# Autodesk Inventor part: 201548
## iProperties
Created: 2007-10
Part Number: 201548
Document SubType Name: Modeling
Designer: TH
Density: 1.06 g/cm^3
Mass: 17.0659 g
Surface Area: 97.1751 cm^2
Volume: 16.0999 cm^3
Material: ABS Plastic
Description: WORM GEAR HOUSING
Component Category: Lower Component
Author: TH
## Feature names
1. Extrusion1
2. Extrusion2
3. Extrusion3
4. Extrusion4
5. Fillet1
6. Fillet2
7. Fillet3
8. Fillet4
9. Extrusion5
10. Fillet5
11. Fillet6
12. Fillet7
13. Extrusion6
14. Extrusion7
15. Fillet8
16. Extrusion8
17. Extrusion9
18. Fillet9
19. Fillet10
20. Revolution1
21. Extrusion10
22. Fillet11
23. Fillet12
